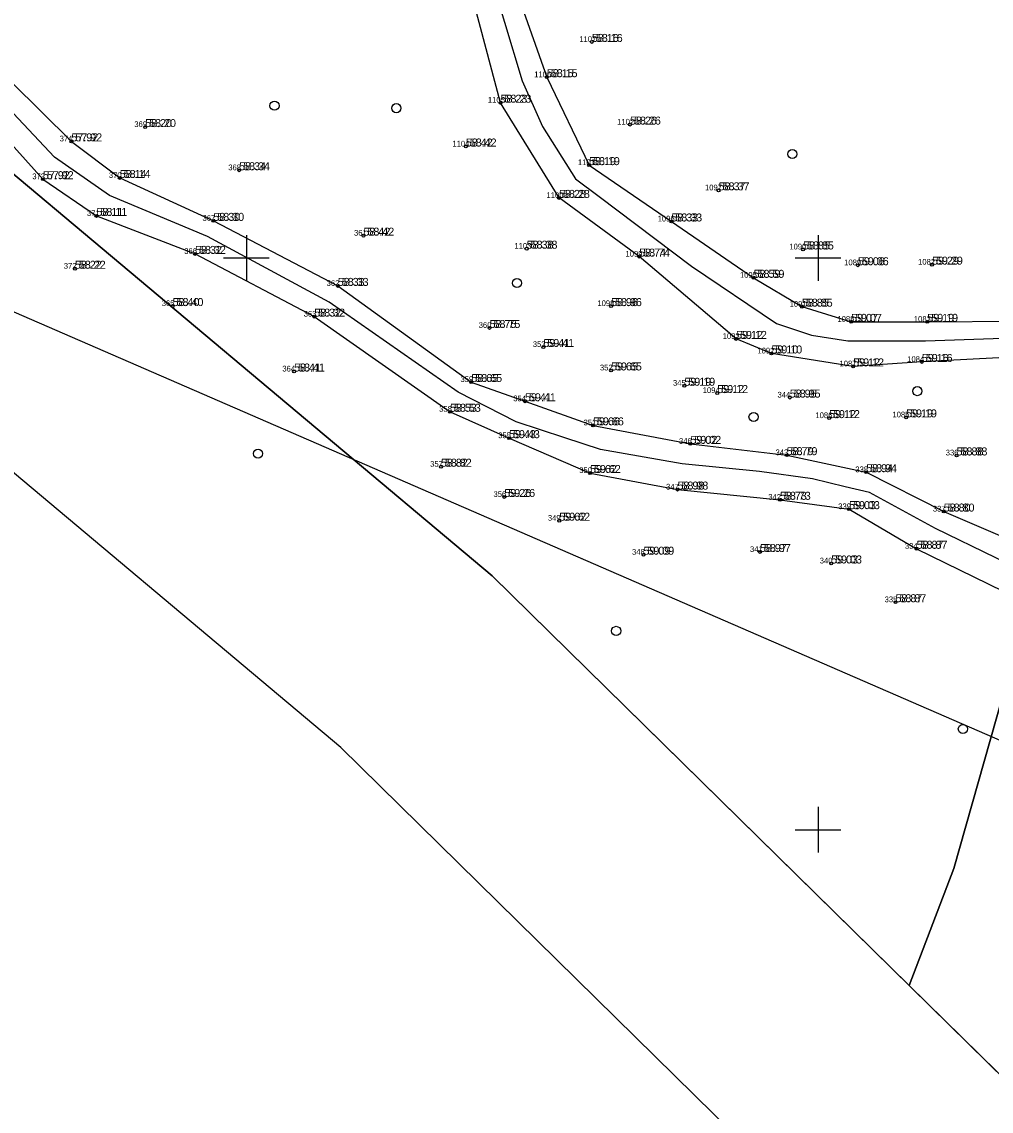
# Model space of a CAD drawing. Extents: x 554846 to 556995, y 6445875 to 6446723.
# Drawn here: x 555130.4 to 555215.1, y 6446025.4 to 6446120.7 of the extents above; entities that cross this region are included whole.
import ezdxf

# ---------------------------------------------------------------- set-up
doc = ezdxf.new("R2010")
doc.units = 0
for name, color, linetype in [('HALJASTUS', 7, 'Continuous'), ('KORGUS-EH2000', 7, 'Continuous'), ('MOOTKORG-EH2000', 7, 'Continuous'), ('MOOTMPUNKT', 7, 'Continuous'), ('MOOTNR', 7, 'Continuous'), ('MOOTPIIR', 7, 'Continuous'), ('PIIR', 7, 'Continuous'), ('TEE', 7, 'Continuous'), ('VORK', 7, 'Continuous')]:
    doc.layers.add(name, color=color, linetype=linetype)

msp = doc.modelspace()

# ---------------------------------------------------------------- linework, layer by layer
at = {"layer": 'HALJASTUS'}
for centre in [(555152.46, 6446113.313), (555163.117, 6446113.098), (555197.75, 6446109.086), (555173.666, 6446097.804), (555208.676, 6446088.353), (555194.359, 6446086.092), (555151.022, 6446082.888), (555182.339, 6446067.385), (555212.667, 6446058.81)]:
    msp.add_circle(centre, 0.4, dxfattribs=at)
at = {"layer": 'KORGUS-EH2000'}
for centre in [(555180.218, 6446118.887), (555176.276, 6446115.804), (555172.224, 6446113.573), (555141.148, 6446111.444), (555183.555, 6446111.659), (555134.694, 6446110.192), (555169.191, 6446109.742), (555149.368, 6446107.667), (555179.97, 6446108.114), (555132.201, 6446106.885), (555138.923, 6446106.992), (555191.304, 6446105.909), (555177.346, 6446105.248), (555136.885, 6446103.671), (555147.112, 6446103.24), (555187.169, 6446103.188), (555160.238, 6446101.947), (555145.513, 6446100.35), (555174.514, 6446100.806), (555184.355, 6446100.114), (555198.686, 6446100.741), (555135.005, 6446099.053), (555203.484, 6446099.359), (555209.969, 6446099.41), (555194.365, 6446098.26), (555157.994, 6446097.552), (555143.549, 6446095.79), (555181.897, 6446095.787), (555198.585, 6446095.738), (555155.937, 6446094.865), (555202.891, 6446094.409), (555209.552, 6446094.41), (555171.268, 6446093.875), (555192.83, 6446092.916), (555175.974, 6446092.21), (555195.92, 6446091.645), (555203.074, 6446090.514), (555209.073, 6446090.903), (555154.171, 6446090.067), (555181.894, 6446090.162), (555169.673, 6446089.148), (555188.306, 6446088.822), (555191.184, 6446088.183), (555197.526, 6446087.787), (555174.368, 6446087.465), (555167.81, 6446086.546), (555200.965, 6446085.991), (555207.702, 6446086.055), (555180.317, 6446085.359), (555172.972, 6446084.239), (555188.834, 6446083.739), (555197.254, 6446082.751), (555212.115, 6446082.728), (555167.019, 6446081.739), (555180.055, 6446081.191), (555204.21, 6446081.262), (555172.559, 6446079.095), (555187.706, 6446079.742), (555196.668, 6446078.85), (555202.713, 6446078.031), (555210.99, 6446077.82), (555177.368, 6446077.019), (555194.92, 6446074.285), (555208.62, 6446074.566), (555184.727, 6446074.045), (555201.146, 6446073.281), (555206.769, 6446069.891)]:
    msp.add_circle(centre, 0.125, dxfattribs=at)
at = {"layer": 'MOOTMPUNKT'}
for centre in [(555180.218, 6446118.887), (555176.276, 6446115.804), (555172.224, 6446113.573), (555141.148, 6446111.444), (555183.555, 6446111.659), (555134.694, 6446110.192), (555169.191, 6446109.742), (555149.368, 6446107.667), (555179.97, 6446108.114), (555132.201, 6446106.885), (555138.923, 6446106.992), (555191.304, 6446105.909), (555177.346, 6446105.248), (555136.885, 6446103.671), (555147.112, 6446103.24), (555187.169, 6446103.188), (555160.238, 6446101.947), (555145.513, 6446100.35), (555174.514, 6446100.806), (555184.355, 6446100.114), (555198.686, 6446100.741), (555135.005, 6446099.053), (555203.484, 6446099.359), (555209.969, 6446099.41), (555194.365, 6446098.26), (555157.994, 6446097.552), (555143.549, 6446095.79), (555181.897, 6446095.787), (555198.585, 6446095.738), (555155.937, 6446094.865), (555202.891, 6446094.409), (555209.552, 6446094.41), (555171.268, 6446093.875), (555192.83, 6446092.916), (555175.974, 6446092.21), (555195.92, 6446091.645), (555203.074, 6446090.514), (555209.073, 6446090.903), (555154.171, 6446090.067), (555181.894, 6446090.162), (555169.673, 6446089.148), (555188.306, 6446088.822), (555191.184, 6446088.183), (555197.526, 6446087.787), (555174.368, 6446087.465), (555167.81, 6446086.546), (555200.965, 6446085.991), (555207.702, 6446086.055), (555180.317, 6446085.359), (555172.972, 6446084.239), (555188.834, 6446083.739), (555197.254, 6446082.751), (555212.115, 6446082.728), (555167.019, 6446081.739), (555180.055, 6446081.191), (555204.21, 6446081.262), (555172.559, 6446079.095), (555187.706, 6446079.742), (555196.668, 6446078.85), (555202.713, 6446078.031), (555210.99, 6446077.82), (555177.368, 6446077.019), (555194.92, 6446074.285), (555208.62, 6446074.566), (555184.727, 6446074.045), (555201.146, 6446073.281), (555206.769, 6446069.891)]:
    msp.add_circle(centre, 0.125, dxfattribs=at)
at = {"layer": 'MOOTPIIR'}
msp.add_lwpolyline([(555318.618, 6446036.416), (555233.239, 6446050.269), (555125.444, 6446097.106), (555048.306, 6446167.69), (555006.11, 6446211.888), (555013.692, 6446244.542), (555031.164, 6446248.5), (555054.569, 6446254.767), (555085.226, 6446285.771), (555124.125, 6446294.677), (555188.077, 6446295.667), (555274.445, 6446293.028)], dxfattribs=at)
at = {"layer": 'PIIR'}
for points in [[(555217.2, 6446027.3), (555207.97, 6446036.37), (555211.87, 6446046.6), (555225.2, 6446093.61), (555227.69, 6446128.87), (555162.59, 6446280.08), (555164.63, 6446323.25), (555170.51, 6446352.86), (555182.27, 6446354.13), (555176.83, 6446322.12), (555175.25, 6446281.89), (555238.76, 6446130.23), (555235.83, 6446092.25), (555221.59, 6446040.5)], [(554929.82, 6446275.15), (554900.05, 6446303.23), (554899.45, 6446307.62), (554900.2, 6446312.5), (554902.6, 6446318.8), (554905.25, 6446321.45), (555070.62, 6446339.03), (555070.32, 6446342.01), (555170.51, 6446352.86), (555164.63, 6446323.25), (555162.59, 6446280.08), (555227.69, 6446128.87), (555225.2, 6446093.61), (555211.87, 6446046.6), (555207.97, 6446036.37), (555171.51, 6446072.2), (555063.52, 6446162.84), (555018.2, 6446200.67), (554979.69, 6446232.72)], [(554905.25, 6446321.45), (554902.6, 6446318.8), (554900.2, 6446312.5), (554899.45, 6446307.62), (554900.05, 6446303.23), (554929.82, 6446275.15), (554979.69, 6446232.72), (555018.2, 6446200.67), (555063.52, 6446162.84), (555171.51, 6446072.2), (555259.76, 6445985.47), (555245.85, 6445971.1), (555158.25, 6446057.2), (555050.97, 6446147.25), (555006.25, 6446184.5), (554967.02, 6446217.23), (554918.28, 6446258.46), (554879.79, 6446294.54), (554861.5, 6446307.3), (554853.6, 6446312.1), (554845.9, 6446314.9)]]:
    msp.add_lwpolyline(points, close=True, dxfattribs=at)
at = {"layer": 'TEE'}
for points in [[(555171.016, 6446125.765), (555174.131, 6446115.486), (555175.904, 6446111.504), (555178.798, 6446106.907), (555180.848, 6446105.365), (555188.922, 6446099.286), (555196.359, 6446094.27), (555199.419, 6446093.256), (555202.6, 6446092.74), (555209.409, 6446092.747), (555217.017, 6446093.016), (555218.682, 6446092.674), (555225.024, 6446091.676), (555228.414, 6446091.49), (555230.683, 6446091.366), (555237.134, 6446089.409), (555240.534, 6446087.672), (555245.997, 6446084.233), (555250.52, 6446082.314), (555255.765, 6446080.541), (555260.831, 6446079.486), (555267.633, 6446078.545)], [(555172.576, 6446126.307), (555176.276, 6446115.804), (555179.97, 6446108.114), (555187.169, 6446103.188), (555194.365, 6446098.26), (555198.585, 6446095.738), (555202.891, 6446094.409), (555209.552, 6446094.41), (555217.445, 6446094.464), (555225.561, 6446093.224), (555229.4, 6446093.92), (555240.115, 6446090.283), (555246.177, 6446086.414), (555256.606, 6446082.386), (555267.961, 6446080.125)], [(555267.574, 6446076.502), (555255.136, 6446078.331), (555244.915, 6446082.585), (555238.588, 6446086.629), (555228.452, 6446089.687), (555225.04, 6446089.968), (555217.5, 6446091.342), (555209.073, 6446090.903), (555203.074, 6446090.514), (555195.92, 6446091.645), (555192.83, 6446092.916), (555184.355, 6446100.114), (555177.346, 6446105.248), (555172.224, 6446113.573), (555169.119, 6446125.329)], [(555124.201, 6446120.525), (555134.694, 6446110.192), (555138.923, 6446106.992), (555147.112, 6446103.24), (555157.994, 6446097.552), (555169.673, 6446089.148), (555174.368, 6446087.465), (555180.317, 6446085.359), (555188.834, 6446083.739), (555197.254, 6446082.751), (555204.21, 6446081.262), (555210.99, 6446077.82), (555221.965, 6446073.13), (555225.614, 6446071.192), (555230.738, 6446067.097), (555239.91, 6446063.522), (555247.335, 6446061.378), (555260.141, 6446058.516), (555267.449, 6446056.625)], [(555276.361, 6446052.392), (555259.849, 6446056.848), (555246.973, 6446059.704), (555239.262, 6446061.875), (555230.339, 6446064.792), (555227.32, 6446066.675), (555224.447, 6446069.239), (555220.829, 6446071.204), (555210.28, 6446076.33), (555204.512, 6446079.474), (555202.383, 6446079.991), (555199.511, 6446080.689), (555194.887, 6446081.333), (555188.127, 6446081.995), (555180.959, 6446083.261), (555177.848, 6446084.274), (555173.596, 6446085.66), (555168.514, 6446088.256), (555157.242, 6446096.118), (555146.605, 6446101.873), (555138.031, 6446105.457), (555133.219, 6446108.823), (555123.24, 6446119.403)], [(555121.821, 6446118.425), (555132.201, 6446106.885), (555136.885, 6446103.671), (555145.513, 6446100.35), (555155.937, 6446094.865), (555167.81, 6446086.546), (555172.972, 6446084.239), (555180.055, 6446081.191), (555187.706, 6446079.742), (555196.668, 6446078.85), (555202.713, 6446078.031), (555208.62, 6446074.566), (555221.204, 6446068.398), (555227.196, 6446063.185), (555238.66, 6446059.992), (555246.439, 6446057.88), (555259.125, 6446054.737), (555266.253, 6446053.038)]]:
    msp.add_lwpolyline(points, dxfattribs=at)
at = {"layer": 'VORK'}
for p, q in [((555150, 6446102), (555150, 6446098)), ((555200, 6446102), (555200, 6446098)), ((555148, 6446100), (555152, 6446100)), ((555198, 6446100), (555202, 6446100)), ((555200, 6446052), (555200, 6446048)), ((555198, 6446050), (555202, 6446050))]:
    msp.add_line(p, q, dxfattribs=at)

# ---------------------------------------------------------------- texts
at = {"layer": 'KORGUS-EH2000'}
for s, p in [('58.16', (555180.568, 6446118.887)), ('58.15', (555176.626, 6446115.804)), ('58.23', (555172.574, 6446113.573)), ('58.20', (555141.498, 6446111.444)), ('58.26', (555183.905, 6446111.659)), ('57.92', (555135.044, 6446110.192)), ('58.42', (555169.541, 6446109.742)), ('58.19', (555180.32, 6446108.114)), ('58.14', (555139.273, 6446106.992)), ('58.34', (555149.718, 6446107.667)), ('57.92', (555132.551, 6446106.885)), ('58.28', (555177.696, 6446105.248)), ('58.37', (555191.654, 6446105.909)), ('58.11', (555137.235, 6446103.671)), ('58.30', (555147.462, 6446103.24)), ('58.33', (555187.519, 6446103.188)), ('58.42', (555160.588, 6446101.947)), ('58.32', (555145.863, 6446100.35)), ('58.38', (555174.864, 6446100.806)), ('58.85', (555199.036, 6446100.741)), ('58.74', (555184.705, 6446100.114)), ('59.06', (555203.834, 6446099.359)), ('59.29', (555210.319, 6446099.41)), ('58.22', (555135.355, 6446099.053)), ('58.33', (555158.344, 6446097.552)), ('58.59', (555194.715, 6446098.26)), ('58.40', (555143.899, 6446095.79)), ('58.96', (555182.247, 6446095.787)), ('58.85', (555198.935, 6446095.738)), ('58.32', (555156.287, 6446094.865)), ('58.75', (555171.618, 6446093.875)), ('59.07', (555203.241, 6446094.409)), ('59.19', (555209.902, 6446094.41)), ('59.12', (555193.18, 6446092.916)), ('59.41', (555176.324, 6446092.21)), ('59.10', (555196.27, 6446091.645)), ('59.16', (555209.423, 6446090.903)), ('58.41', (555154.521, 6446090.067)), ('59.65', (555182.244, 6446090.162)), ('59.12', (555203.424, 6446090.514)), ('58.65', (555170.023, 6446089.148)), ('59.19', (555188.656, 6446088.822)), ('59.12', (555191.534, 6446088.183)), ('59.41', (555174.718, 6446087.465)), ('58.95', (555197.876, 6446087.787)), ('58.53', (555168.16, 6446086.546)), ('59.12', (555201.315, 6446085.991)), ('59.19', (555208.052, 6446086.055)), ('59.66', (555180.667, 6446085.359)), ('59.43', (555173.322, 6446084.239)), ('59.02', (555189.184, 6446083.739)), ('58.79', (555197.604, 6446082.751)), ('58.88', (555212.465, 6446082.728)), ('58.82', (555167.369, 6446081.739)), ('58.94', (555204.56, 6446081.262)), ('59.62', (555180.405, 6446081.191)), ('58.98', (555188.056, 6446079.742)), ('59.26', (555172.909, 6446079.095)), ('58.73', (555197.018, 6446078.85)), ('59.03', (555203.063, 6446078.031)), ('58.80', (555211.34, 6446077.82)), ('59.62', (555177.718, 6446077.019)), ('58.87', (555208.97, 6446074.566)), ('59.09', (555185.077, 6446074.045)), ('58.97', (555195.27, 6446074.285)), ('59.03', (555201.496, 6446073.281)), ('58.87', (555207.119, 6446069.891))]:
    msp.add_text(s, height=0.7, dxfattribs=at).set_placement(p)
at = {"layer": 'MOOTKORG-EH2000'}
for s, p in [('58.16', (555180.218, 6446118.887)), ('58.15', (555176.276, 6446115.804)), ('58.23', (555172.224, 6446113.573)), ('58.20', (555141.148, 6446111.444)), ('58.26', (555183.555, 6446111.659)), ('57.92', (555134.694, 6446110.192)), ('58.42', (555169.191, 6446109.742)), ('58.19', (555179.97, 6446108.114)), ('58.14', (555138.923, 6446106.992)), ('58.34', (555149.368, 6446107.667)), ('57.92', (555132.201, 6446106.885)), ('58.28', (555177.346, 6446105.248)), ('58.37', (555191.304, 6446105.909)), ('58.11', (555136.885, 6446103.671)), ('58.30', (555147.112, 6446103.24)), ('58.33', (555187.169, 6446103.188)), ('58.42', (555160.238, 6446101.947)), ('58.32', (555145.513, 6446100.35)), ('58.38', (555174.514, 6446100.806)), ('58.85', (555198.686, 6446100.741)), ('58.74', (555184.355, 6446100.114)), ('59.06', (555203.484, 6446099.359)), ('59.29', (555209.969, 6446099.41)), ('58.22', (555135.005, 6446099.053)), ('58.33', (555157.994, 6446097.552)), ('58.59', (555194.365, 6446098.26)), ('58.40', (555143.549, 6446095.79)), ('58.96', (555181.897, 6446095.787)), ('58.85', (555198.585, 6446095.738)), ('58.32', (555155.937, 6446094.865)), ('58.75', (555171.268, 6446093.875)), ('59.07', (555202.891, 6446094.409)), ('59.19', (555209.552, 6446094.41)), ('59.12', (555192.83, 6446092.916)), ('59.41', (555175.974, 6446092.21)), ('59.10', (555195.92, 6446091.645)), ('59.16', (555209.073, 6446090.903)), ('58.41', (555154.171, 6446090.067)), ('59.65', (555181.894, 6446090.162)), ('59.12', (555203.074, 6446090.514)), ('58.65', (555169.673, 6446089.148)), ('59.19', (555188.306, 6446088.822)), ('59.12', (555191.184, 6446088.183)), ('59.41', (555174.368, 6446087.465)), ('58.95', (555197.526, 6446087.787)), ('58.53', (555167.81, 6446086.546)), ('59.12', (555200.965, 6446085.991)), ('59.19', (555207.702, 6446086.055)), ('59.66', (555180.317, 6446085.359)), ('59.43', (555172.972, 6446084.239)), ('59.02', (555188.834, 6446083.739)), ('58.79', (555197.254, 6446082.751)), ('58.88', (555212.115, 6446082.728)), ('58.82', (555167.019, 6446081.739)), ('58.94', (555204.21, 6446081.262)), ('59.62', (555180.055, 6446081.191)), ('58.98', (555187.706, 6446079.742)), ('59.26', (555172.559, 6446079.095)), ('58.73', (555196.668, 6446078.85)), ('59.03', (555202.713, 6446078.031)), ('58.80', (555210.99, 6446077.82)), ('59.62', (555177.368, 6446077.019)), ('58.87', (555208.62, 6446074.566)), ('59.09', (555184.727, 6446074.045)), ('58.97', (555194.92, 6446074.285)), ('59.03', (555201.146, 6446073.281)), ('58.87', (555206.769, 6446069.891))]:
    msp.add_text(s, height=0.7, dxfattribs=at).set_placement(p)
at = {"layer": 'MOOTNR'}
for s, p in [('1107', (555179.118, 6446118.887)), ('1106', (555175.176, 6446115.804)), ('1105', (555171.124, 6446113.573)), ('369', (555140.198, 6446111.444)), ('1102', (555182.43, 6446111.659)), ('374', (555133.669, 6446110.192)), ('1104', (555168.016, 6446109.742)), ('1101', (555178.995, 6446108.114)), ('368', (555148.418, 6446107.667)), ('373', (555131.276, 6446106.885)), ('370', (555137.973, 6446106.992)), ('1100', (555176.246, 6446105.248)), ('1097', (555190.104, 6446105.909)), ('371', (555136.06, 6446103.671)), ('367', (555146.162, 6446103.24)), ('1096', (555185.969, 6446103.188)), ('361', (555159.413, 6446101.947)), ('1103', (555173.439, 6446100.806)), ('1090', (555197.486, 6446100.741)), ('366', (555144.563, 6446100.35)), ('1099', (555183.155, 6446100.114)), ('372', (555134.03, 6446099.053)), ('1089', (555202.284, 6446099.359)), ('1082', (555208.744, 6446099.41)), ('1095', (555193.165, 6446098.26)), ('362', (555157.019, 6446097.552)), ('365', (555142.599, 6446095.79)), ('1098', (555180.697, 6446095.787)), ('1091', (555197.51, 6446095.738)), ('363', (555155.012, 6446094.865)), ('360', (555170.318, 6446093.875)), ('1088', (555201.691, 6446094.409)), ('1083', (555208.377, 6446094.41)), ('1093', (555191.655, 6446092.916)), ('353', (555175.049, 6446092.21)), ('1092', (555194.695, 6446091.645)), ('364', (555153.146, 6446090.067)), ('352', (555180.919, 6446090.162)), ('1087', (555201.874, 6446090.514)), ('1084', (555207.798, 6446090.903)), ('359', (555168.723, 6446089.148)), ('345', (555187.306, 6446088.822)), ('1094', (555189.909, 6446088.183)), ('354', (555173.343, 6446087.465)), ('344', (555196.451, 6446087.787)), ('358', (555166.86, 6446086.546)), ('351', (555179.492, 6446085.359)), ('1086', (555199.765, 6446085.991)), ('1085', (555206.502, 6446086.055)), ('355', (555172.022, 6446084.239)), ('346', (555187.834, 6446083.739)), ('343', (555196.279, 6446082.751)), ('336', (555211.165, 6446082.728)), ('357', (555166.069, 6446081.739)), ('350', (555179.105, 6446081.191)), ('338', (555203.26, 6446081.262)), ('347', (555186.706, 6446079.742)), ('356', (555171.609, 6446079.095)), ('342', (555195.643, 6446078.85)), ('339', (555201.763, 6446078.031)), ('337', (555210.04, 6446077.82)), ('349', (555176.368, 6446077.019)), ('348', (555183.727, 6446074.045)), ('341', (555194.045, 6446074.285)), ('334', (555207.595, 6446074.566)), ('340', (555200.146, 6446073.281)), ('335', (555205.819, 6446069.891))]:
    msp.add_text(s, height=0.5, dxfattribs=at).set_placement(p)

doc.saveas('drawing.dxf')
